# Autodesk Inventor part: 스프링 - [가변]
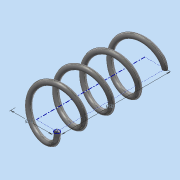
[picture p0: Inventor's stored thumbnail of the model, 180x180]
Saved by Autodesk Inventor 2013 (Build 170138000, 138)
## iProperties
Created: 2015-09
Part Number: 스프링 - [가변]
Material: 강철, 탄소
Document SubType Name: Modeling
Designer: Administrator
Density: 7.87 g/cm^3
Mass: 4.92096 g
Surface Area: 12.7475 cm^2
Volume: 0.625281 cm^3
Author: Administrator
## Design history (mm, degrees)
sketch "스케치1"
  geometry: L1 (0, 0)-(8, 0); L2 (8, 0)-(8, 42); L3 (8, 42)-(0, 42); L4 (0, 42)-(0, 0); C1 r 1 at (8, 0)
  constraints: 8 end point, 2 parallel, 1 centre point, 1 coincident, 1 horizontal, 1 perpendicular
  dimensions: "d0" = 2 diameter of C1; "d2" = 42 distance between parallel lines of L1 L3 (derived); "d3" = 16 diameter of L2 L4
feature "코일1" pitch "d4" = 10; turns "d6" = 4; dims "d5" = 42 (= d2), "d7" = 0, angle "d8" = 90 deg, angle "d9" = 90 deg, "d10" = 0, "d11" = 0
sketch "스케치2"
  geometry: L1 (-9, 0)-(-7, 0) reference; L2 (-9, 0)-(-7, 0) reference; 1 further point
  constraints: 2 horizontal alignment
extrude "돌출1" cut sketch "스케치2" distance "d12" = 10; taper "d13" = 0 deg
node "작업 평면1"
sketch "스케치3"
  geometry: L1 (2, 0)-(0, 0) reference; 1 further point
  constraints: 1 horizontal alignment
extrude "돌출2" cut sketch "스케치3" distance "d14" = 10; taper "d15" = 0 deg
node "솔리드1"
node "절단 모서리 투영1"
node "절단 모서리 투영2"
node "절단 모서리 투영3"
